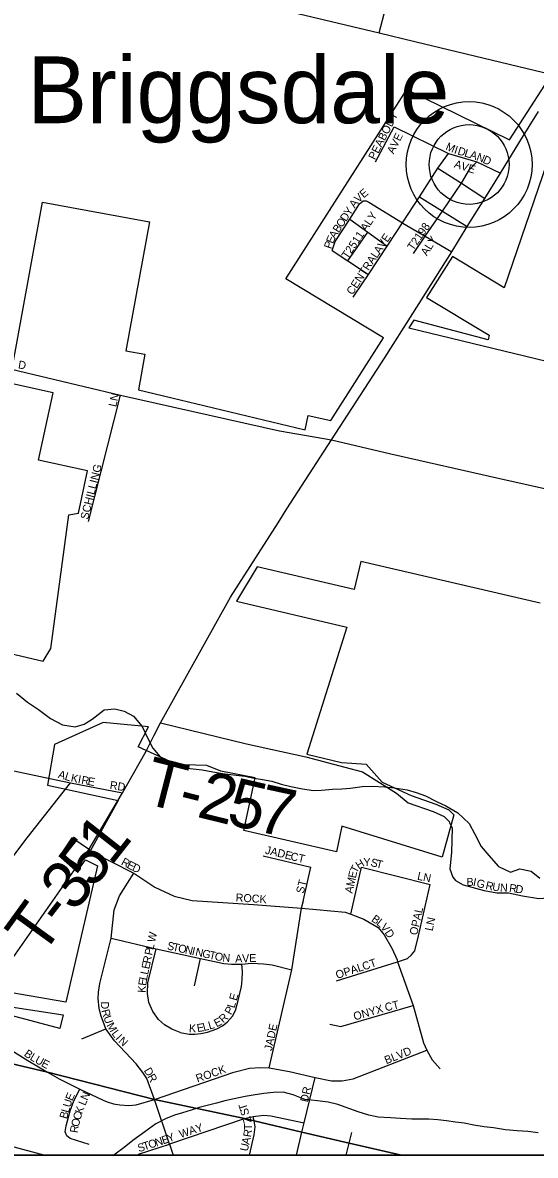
# Model space of a CAD drawing. Extents: x 0 to 34, y -6.2 to 22.
# Drawn here: x 3.061 to 3.667, y 14.39 to 15.73 of the extents above; entities that cross this region are included whole.
import ezdxf

# ---------------------------------------------------------------- set-up
doc = ezdxf.new("R2010")
doc.units = 0
for name, color, linetype in [('GM_X_City_Street', 7, 'Continuous'), ('GM_X_City_Street_Text', 7, 'Continuous'), ('GM_X_Corporation', 7, 'Continuous'), ('GM_X_County_Road', 7, 'Continuous'), ('GM_X_Minor_River', 7, 'Continuous'), ('GM_X_Township', 7, 'Continuous'), ('GM_X_Township_Road', 7, 'Continuous'), ('GM_X_Township_Road_Text', 7, 'Continuous'), ('GM_X_Township_Subdivision', 7, 'Continuous'), ('GM_X_Township_Subdivision_Text', 7, 'Continuous'), ('GM_X_Unincorporated', 7, 'Continuous'), ('GM_X_Unincorporated_Text', 7, 'Continuous'), ('GM_X_US_Route', 7, 'Continuous'), ('SH_Data', 7, 'Continuous')]:
    doc.layers.add(name, color=color, linetype=linetype)

msp = doc.modelspace()

# ---------------------------------------------------------------- linework, layer by layer
at = {"layer": 'GM_X_City_Street'}
for points in [[(2.2755, 16.0058), (2.3978, 15.9667), (2.514, 15.9401), (2.5743, 15.9266), (2.6337, 15.9133), (2.6968, 15.899), (2.7428, 15.8886), (2.791, 15.8777), (2.8428, 15.8659), (2.944, 15.8431), (3.0941, 15.8092), (3.2256, 15.7796), (3.2773, 15.7671), (3.3381, 15.7525), (3.4823, 15.7179), (3.5243, 15.7078), (3.6965, 15.6665)], [(3.4823, 15.7179), (3.5118, 15.831)], [(3.1001, 14.8344), (3.1174, 14.8308), (3.1788, 14.8191)], [(3.5655, 14.7836), (3.5685, 14.7776), (3.5675, 14.7483), (3.5658, 14.729), (3.5692, 14.7194), (3.5725, 14.7152), (3.5816, 14.7102), (3.6062, 14.7036), (3.6214, 14.7008), (3.6351, 14.7007), (3.6517, 14.6971), (3.6711, 14.6939), (3.6931, 14.6957), (3.6988, 14.6956), (3.7052, 14.6933), (3.7139, 14.691), (3.723, 14.6882), (3.724, 14.688), (3.7252, 14.6878)], [(3.1385, 14.7514), (3.1922, 14.724), (3.2168, 14.7076), (3.2398, 14.6968), (3.2609, 14.6915), (3.3334, 14.6869), (3.3904, 14.6824), (3.4081, 14.681), (3.4419, 14.6777), (3.4486, 14.6753), (3.4642, 14.6696), (3.4808, 14.6596), (3.488, 14.6512), (3.4973, 14.6352), (3.5033, 14.6214), (3.5038, 14.6193), (3.5224, 14.5673), (3.5346, 14.5232), (3.5384, 14.5145), (3.5448, 14.503), (3.5542, 14.4926)], [(3.3449, 14.7446), (3.4013, 14.7312)], [(3.3925, 14.6918), (3.3927, 14.6926), (3.4013, 14.7312)], [(3.4486, 14.6753), (3.4613, 14.7312), (3.5423, 14.7104)], [(3.2342, 14.4035), (3.2164, 14.4564), (3.2074, 14.4812), (3.2029, 14.488), (3.195, 14.4984), (3.1694, 14.5255), (3.159, 14.5398), (3.153, 14.556), (3.1512, 14.5644), (3.15, 14.5753), (3.1502, 14.5834), (3.152, 14.5933), (3.1651, 14.6471), (3.1687, 14.6806), (3.1753, 14.6972), (3.1845, 14.712), (3.1922, 14.724)], [(3.5038, 14.6193), (3.5155, 14.6232), (3.5204, 14.6274), (3.5243, 14.6323), (3.5286, 14.6497), (3.5423, 14.7104)], [(3.3521, 14.4938), (3.3788, 14.6096), (3.3904, 14.6824), (3.3925, 14.6918)], [(3.1651, 14.6471), (3.2183, 14.6344), (3.2709, 14.6229), (3.2986, 14.6171), (3.3077, 14.6162), (3.3197, 14.6164), (3.3311, 14.6174), (3.3454, 14.6169), (3.3556, 14.6154), (3.3788, 14.6096)], [(3.247, 14.5354), (3.2369, 14.5394), (3.2284, 14.5445), (3.2214, 14.5507), (3.2145, 14.5602), (3.2097, 14.5709), (3.2081, 14.5818), (3.2087, 14.5943), (3.2183, 14.6344)], [(3.2637, 14.5906), (3.2709, 14.6229)], [(3.4318, 14.5965), (3.5038, 14.6193)], [(3.247, 14.5354), (3.2575, 14.5337), (3.2642, 14.5335), (3.2714, 14.5342), (3.2791, 14.536), (3.2901, 14.5399), (3.297, 14.5433), (3.3026, 14.5478), (3.3088, 14.5547), (3.3124, 14.5616), (3.3155, 14.5732), (3.3193, 14.5901), (3.3202, 14.5977), (3.3204, 14.6078), (3.3197, 14.6164)], [(3.4237, 14.5453), (3.437, 14.5428), (3.5224, 14.5673)], [(2.9945, 14.5473), (3.0668, 14.5025), (3.0901, 14.4886), (3.1037, 14.4805), (3.1283, 14.4686), (3.156, 14.4553), (3.1605, 14.4535), (3.1682, 14.4513), (3.1756, 14.4499), (3.1861, 14.4491), (3.1949, 14.45), (3.2164, 14.4564), (3.3102, 14.4887), (3.3289, 14.4933), (3.3419, 14.4941), (3.3521, 14.4938), (3.3763, 14.4893), (3.4064, 14.4824), (3.4257, 14.4785), (3.4385, 14.4785), (3.4515, 14.4806), (3.5384, 14.5145)], [(3.1307, 14.5282), (3.159, 14.5398)], [(3.3844, 14.3902), (3.3909, 14.4178), (3.3936, 14.4288), (3.4064, 14.4824)], [(3.1393, 14.4031), (3.1169, 14.41), (3.1128, 14.4132), (3.111, 14.4181), (3.1122, 14.4249), (3.117, 14.443), (3.1212, 14.4546), (3.1283, 14.4686)], [(3.2347, 14.4037), (3.3231, 14.4338), (3.3332, 14.4362), (3.3459, 14.4378), (3.3541, 14.437), (3.3936, 14.4288)], [(3.3287, 14.3902), (3.3343, 14.4143), (3.3356, 14.4238), (3.3342, 14.4312), (3.3332, 14.4362)], [(3.4431, 14.3902), (3.4466, 14.4047), (3.4497, 14.4171)], [(3.1977, 14.3915), (3.2342, 14.4035), (3.2347, 14.4037)], [(3.2342, 14.4035), (3.2385, 14.3902)]]:
    msp.add_lwpolyline(points, dxfattribs=at)
at = {"layer": 'GM_X_Corporation'}
msp.add_line((3.0868, 14.3902), (3.8052, 14.3902), dxfattribs=at)
for points in [[(3.0189, 14.9901), (3.0848, 14.9747), (3.0939, 14.9898), (3.1154, 15.148), (3.1266, 15.1499), (3.1375, 15.1999), (3.0793, 15.2127), (3.0967, 15.2922), (3.0449, 15.3036), (3.0841, 15.5179), (3.2108, 15.4947), (3.1828, 15.3419), (3.2051, 15.3378), (3.1975, 15.2959), (3.3946, 15.2486), (3.3984, 15.2653), (3.4251, 15.2593), (3.4872, 15.3574), (3.3717, 15.4272), (3.5148, 15.651), (3.6363, 15.5914), (3.6781, 15.6561)], [(3.7056, 15.6375), (3.63, 15.4164), (3.5687, 15.4535), (3.5383, 15.4048), (3.6123, 15.3603), (3.6111, 15.3549), (3.5231, 15.3782), (3.5174, 15.369), (4.3458, 15.1683)], [(3.6725, 15.0433), (3.4604, 15.0927), (3.4527, 15.0595), (3.338, 15.0862), (3.3135, 15.0456), (3.4438, 15.0151), (3.3965, 14.8649), (3.4376, 14.8549), (3.45, 14.8541), (3.4668, 14.853), (3.4857, 14.8316), (3.5199, 14.816), (3.5493, 14.8056), (3.5644, 14.799), (3.5706, 14.7931), (3.5565, 14.743), (3.4379, 14.7797), (3.4316, 14.7494), (3.3223, 14.7746), (3.3355, 14.8369), (3.295, 14.8447), (3.2783, 14.8515), (3.2514, 14.852), (3.2351, 14.856), (3.1972, 14.8736), (3.2096, 14.897), (3.1558, 14.9022), (3.0981, 14.8761), (3.0899, 14.8279), (3.1734, 14.81), (3.1408, 14.7508), (3.1188, 14.7658), (3.106, 14.747), (3.1289, 14.7313), (3.1348, 14.7399), (3.1491, 14.7326), (3.1118, 14.5712), (3.0366, 14.5846)], [(3.0258, 14.5691), (3.1084, 14.5564), (3.1047, 14.5403), (3.0469, 14.5558)], [(2.8818, 14.3902), (2.918, 14.4415), (2.9386, 14.4646), (2.9843, 14.4515), (2.9764, 14.4198), (3.0868, 14.3902)]]:
    msp.add_lwpolyline(points, dxfattribs=at)
at = {"layer": 'GM_X_County_Road'}
for points in [[(3.0476, 15.3204), (3.1764, 15.2894), (3.3645, 15.2473), (3.4258, 15.2365)], [(3.4258, 15.2365), (3.4961, 15.2199), (3.625, 15.1908), (3.759, 15.1611), (3.7743, 15.1577), (3.7928, 15.1515), (3.84, 15.1281), (3.8645, 15.116), (3.9154, 15.0908), (3.9554, 15.0774), (4.0318, 15.0667), (4.1118, 15.0579), (4.1129, 15.0578), (4.1954, 15.041), (4.1993, 15.0402)], [(2.9923, 14.8574), (3.1001, 14.8344)]]:
    msp.add_lwpolyline(points, dxfattribs=at)
at = {"layer": 'GM_X_Minor_River'}
for points in [[(3.0532, 14.9368), (3.0664, 14.9264), (3.0795, 14.9175), (3.0934, 14.907), (3.1077, 14.8996), (3.1228, 14.8971), (3.1335, 14.9004), (3.143, 14.906), (3.1572, 14.9172)], [(3.1572, 14.9172), (3.1697, 14.9185), (3.1807, 14.9157), (3.1916, 14.9099), (3.202, 14.8976), (3.2087, 14.8834), (3.2146, 14.872), (3.225, 14.8593), (3.2355, 14.8538), (3.2453, 14.8507), (3.2586, 14.8478), (3.273, 14.8461), (3.2854, 14.844), (3.2968, 14.842), (3.313, 14.8399), (3.3233, 14.8386), (3.3342, 14.8365), (3.3444, 14.8349), (3.3554, 14.8328), (3.3663, 14.8293), (3.3777, 14.8265), (3.3916, 14.8236), (3.4045, 14.8219), (3.414, 14.8222), (3.4269, 14.8235), (3.4379, 14.8237), (3.4481, 14.8247), (3.4622, 14.8264), (3.4735, 14.8271), (3.4887, 14.8261), (3.5, 14.8248), (3.5152, 14.8227), (3.5257, 14.8195), (3.5371, 14.8156), (3.5499, 14.8089), (3.5611, 14.8035), (3.5751, 14.7953), (3.5885, 14.7826), (3.5952, 14.77), (3.6029, 14.7554), (3.6119, 14.7447), (3.6231, 14.732), (3.6374, 14.7253), (3.6484, 14.729), (3.6617, 14.7265), (3.6722, 14.718)], [(3.67, 14.417), (3.6578, 14.4183), (3.6454, 14.4192), (3.6317, 14.4205), (3.6174, 14.4226), (3.6064, 14.4239), (3.5939, 14.426), (3.5826, 14.4281), (3.5724, 14.4293), (3.5618, 14.431), (3.5515, 14.4323), (3.5409, 14.4328), (3.5209, 14.4331), (3.5072, 14.4336), (3.4955, 14.4346), (3.4811, 14.4355), (3.4698, 14.4379), (3.4573, 14.4415), (3.4332, 14.4502), (3.4218, 14.453), (3.4094, 14.4547), (3.3942, 14.4564), (3.3806, 14.4616), (3.3686, 14.4648), (3.3572, 14.4645), (3.3458, 14.4632), (3.3333, 14.4614), (3.3238, 14.4597), (3.3109, 14.4572), (3.2998, 14.4547), (3.2899, 14.4518), (3.2789, 14.4493), (3.2694, 14.4467), (3.2599, 14.4438), (3.2496, 14.4406), (3.2401, 14.4377), (3.2294, 14.4332), (3.218, 14.4273), (3.205, 14.418), (3.1908, 14.4076), (3.1805, 14.3994), (3.1701, 14.3915), (3.1683, 14.3902)]]:
    msp.add_lwpolyline(points, dxfattribs=at)
at = {"layer": 'GM_X_Township'}
msp.add_line((3.5084, 14.3902), (6.1932, 14.3902), dxfattribs=at)
for points in [[(2.2755, 14.6804), (2.2868, 14.6777), (2.9712, 14.5166), (3.0901, 14.4886), (3.2164, 14.4564), (3.3231, 14.4338), (3.3342, 14.4312), (3.3909, 14.4178), (3.4466, 14.4047), (3.5084, 14.3902)], [(2.2755, 14.6804), (2.2755, 14.3902), (3.5084, 14.3902)], [(3.5084, 14.3902), (3.4466, 14.4047), (3.3909, 14.4178), (3.3342, 14.4312), (3.3231, 14.4338), (3.2164, 14.4564), (3.0901, 14.4886), (2.9712, 14.5166), (2.2868, 14.6777), (2.2755, 14.6804)]]:
    msp.add_lwpolyline(points, dxfattribs=at)
at = {"layer": 'GM_X_Township_Road'}
for points in [[(3.2236, 14.9019), (3.3253, 14.8771), (3.3953, 14.8616), (3.4414, 14.8493), (3.4623, 14.8438), (3.5028, 14.8186), (3.5163, 14.8072), (3.5458, 14.7968), (3.5591, 14.791), (3.5643, 14.786), (3.5648, 14.7851), (3.5655, 14.7836)], [(2.9201, 14.6707), (2.9389, 14.6668), (2.9731, 14.6616), (2.9923, 14.6583), (2.9939, 14.6649), (3.0029, 14.6849), (3.0115, 14.6955), (3.0258, 14.713), (3.0658, 14.7658), (3.1174, 14.8308)]]:
    msp.add_lwpolyline(points, dxfattribs=at)
at = {"layer": 'GM_X_Township_Subdivision'}
for points in [[(3.4777, 15.5654), (3.4997, 15.6067)], [(3.4997, 15.6067), (3.5643, 15.5754), (3.5977, 15.5653), (3.6255, 15.5522)], [(3.5022, 15.4818), (3.5097, 15.4933), (3.5297, 15.5241), (3.5516, 15.5579), (3.5643, 15.5754)], [(3.5228, 15.4572), (3.5366, 15.4774), (3.5569, 15.5072), (3.5793, 15.5401), (3.5891, 15.5565), (3.5977, 15.5653)], [(3.5516, 15.5579), (3.5793, 15.5401), (3.6071, 15.5222)], [(3.4264, 15.4605), (3.4276, 15.464), (3.4303, 15.4712), (3.4473, 15.4978), (3.4587, 15.5158), (3.4633, 15.5192)], [(3.4633, 15.5192), (3.4667, 15.5192), (3.4701, 15.5176), (3.5097, 15.4933), (3.5102, 15.493), (3.5366, 15.4774), (3.5679, 15.4591)], [(3.5297, 15.5241), (3.5569, 15.5072), (3.5863, 15.489)], [(3.4473, 15.4978), (3.4687, 15.4822), (3.4915, 15.4657)], [(3.4452, 15.4482), (3.4687, 15.4822)], [(3.4627, 15.4223), (3.4694, 15.4323), (3.4915, 15.4657), (3.5022, 15.4818), (3.5022, 15.4818)], [(3.4264, 15.4605), (3.4452, 15.4482), (3.4694, 15.4323)], [(3.4514, 15.4052), (3.4627, 15.4223), (3.4627, 15.4223)], [(3.1385, 15.14), (3.1764, 15.2894)]]:
    msp.add_lwpolyline(points, dxfattribs=at)
at = {"layer": 'GM_X_Unincorporated'}
for radius in [0.0744, 0.0472]:
    msp.add_circle((3.5885, 15.5623), radius, dxfattribs=at)
at = {"layer": 'GM_X_US_Route'}
for points in [[(3.6243, 15.5503), (3.6255, 15.5522), (3.6486, 15.5896), (3.6707, 15.625)], [(3.4843, 15.3267), (3.4885, 15.3332), (3.5221, 15.3861), (3.5679, 15.4591), (3.5863, 15.489), (3.6071, 15.5222), (3.6243, 15.5503)], [(3.3626, 15.1386), (3.3729, 15.1548), (3.4258, 15.2365), (3.4843, 15.3267)], [(3.2161, 14.8871), (3.2236, 14.9019), (3.3064, 15.0506), (3.3626, 15.1386)], [(3.2074, 14.8698), (3.2161, 14.8871)], [(3.1836, 14.8275), (3.2067, 14.8684), (3.2074, 14.8698)], [(3.1408, 14.7553), (3.1788, 14.8191), (3.1836, 14.8275)], [(3.135, 14.7465), (3.1385, 14.7514), (3.1408, 14.7553)], [(2.9881, 14.5388), (2.9945, 14.5473), (3.0467, 14.6204), (3.135, 14.7465)]]:
    msp.add_lwpolyline(points, dxfattribs=at)
at = {"layer": 'SH_Data'}
msp.add_lwpolyline([(9.0755, 21.1902), (9.0755, 14.3902), (2.2755, 14.3902), (2.2755, 21.1902)], close=True, dxfattribs=at)

# ---------------------------------------------------------------- texts
at = {"layer": 'GM_X_City_Street_Text'}
for s, rotation, p in [('D', 350.2289, (3.0548, 15.3213)), ('A', 343.0789, (3.1018, 14.837)), ('L', 343.0872, (3.1097, 14.8346)), ('K', 347.8693, (3.117, 14.8325)), ('I', 349.559, (3.1254, 14.8306)), ('R', 349.6937, (3.1295, 14.8299)), ('E', 349.6932, (3.1369, 14.8285)), ('RD', 351.0327, (3.1632, 14.8238)), ('JADE', 346.3728, (3.3467, 14.7472)), ('R', 331.469, (3.1763, 14.7345)), ('CT', 347.4648, (3.3766, 14.7397)), ('H', 31.9943, (3.4579, 14.7283)), ('Y', 1.58, (3.4637, 14.7323)), ('S', 346.3728, (3.4714, 14.7326)), ('T', 346.3728, (3.4778, 14.731)), ('E', 331.455, (3.1829, 14.7309)), ('D', 334.1463, (3.1892, 14.7275)), ('E', 77.6158, (3.4545, 14.7174)), ('T', 62.4086, (3.4557, 14.7233)), ('ST', 75.9573, (3.3928, 14.6992)), ('M', 77.6158, (3.4523, 14.7076)), ('LN', 348.1073, (3.5266, 14.7164)), ('B', 1.7489, (3.5856, 14.7088)), ('I', 348.2442, (3.5925, 14.7091)), ('G', 345.2375, (3.5965, 14.7082)), ('R', 347.2109, (3.6073, 14.7054)), ('U', 351.8179, (3.6154, 14.7036)), ('ROCK', 356.4997, (3.3123, 14.6906)), ('A', 77.6158, (3.4505, 14.6995)), ('N', 358.3377, (3.6249, 14.7023)), ('R', 352.4744, (3.6354, 14.702)), ('D', 351.2023, (3.6428, 14.7011)), ('B', 324.9423, (3.4722, 14.6678)), ('OPAL', 77.4718, (3.527, 14.65)), ('L', 321.2335, (3.4782, 14.6636)), ('V', 309.9707, (3.483, 14.6598)), ('LN', 78.1183, (3.5453, 14.655)), ('W', 77.8031, (3.2171, 14.6416)), ('D', 304.2114, (3.4882, 14.6536)), ('P', 77.806, (3.2137, 14.6262)), ('L', 77.7793, (3.2152, 14.6327)), ('S', 347.6668, (3.2308, 14.6339)), ('T', 347.6668, (3.2373, 14.6324)), ('O', 347.6442, (3.2438, 14.631)), ('N', 347.6618, (3.252, 14.6292)), ('I', 347.6182, (3.2601, 14.6275)), ('N', 347.684, (3.2642, 14.6266)), ('G', 347.6442, (3.2723, 14.6248)), ('E', 77.8138, (3.2102, 14.6099)), ('R', 77.7899, (3.2116, 14.6164)), ('T', 347.6644, (3.2805, 14.623)), ('O', 347.6656, (3.287, 14.6216)), ('N', 355.9282, (3.2966, 14.6196)), ('A', 2.3395, (3.312, 14.6181)), ('V', 2.3493, (3.3203, 14.6184)), ('E', 1.1201, (3.3286, 14.6188)), ('CT', 19.4394, (3.464, 14.6088)), ('L', 77.7793, (3.2088, 14.6033)), ('OPAL', 17.9243, (3.4324, 14.5988)), ('E', 82.9055, (3.2067, 14.5904)), ('L', 78.6418, (3.2075, 14.5968)), ('K', 85.9751, (3.2061, 14.5822)), ('E', 73.7313, (3.3136, 14.5725)), ('D', 272.6671, (3.153, 14.572)), ('P', 60.5137, (3.3069, 14.5557)), ('L', 73.715, (3.311, 14.5637)), ('ONYX', 16.1457, (3.4532, 14.5497)), ('CT', 13.2348, (3.49, 14.5605)), ('R', 284.1466, (3.1537, 14.5617)), ('U', 290.2566, (3.1559, 14.5534)), ('E', 27.9631, (3.2899, 14.5415)), ('R', 42.6607, (3.2979, 14.5462)), ('M', 299.6919, (3.1595, 14.544)), ('L', 307.936, (3.1652, 14.5341)), ('K', 359.1912, (3.2572, 14.5358)), ('E', 9.4647, (3.2674, 14.5359)), ('L', 14.0851, (3.2748, 14.5371)), ('L', 16.4924, (3.2816, 14.5389)), ('JADE', 78.0242, (3.3553, 14.5133)), ('I', 312.6288, (3.1699, 14.5282)), ('N', 316.7562, (3.1732, 14.5246)), ('B', 324.612, (3.0615, 14.5085)), ('BLVD', 21.8014, (3.4906, 14.4979)), ('L', 329.8033, (3.0684, 14.5037)), ('U', 331.4894, (3.0744, 14.5002)), ('E', 331.562, (3.0818, 14.4962)), ('D', 300.5365, (3.2036, 14.4906)), ('R', 297.7597, (3.2078, 14.4835)), ('ROCK', 19.1814, (3.2673, 14.4763)), ('E', 66.1235, (3.1193, 14.4539)), ('N', 65.8111, (3.1371, 14.4544)), ('DR', 77.4789, (3.3978, 14.4525)), ('L', 73.4019, (3.115, 14.4398)), ('U', 72.5951, (3.1169, 14.4462)), ('K', 70.5212, (3.1309, 14.4383)), ('L', 67.2246, (3.1346, 14.4483)), ('T', 107.0975, (3.327, 14.4452)), ('S', 107.0582, (3.3289, 14.4388)), ('B', 73.3775, (3.1129, 14.4326)), ('O', 75.3276, (3.1268, 14.4232)), ('C', 74.108, (3.1289, 14.4312)), ('Z', 104.9126, (3.3315, 14.4296)), ('R', 80.362, (3.1256, 14.4161)), ('WAY', 17.8768, (3.2474, 14.4105)), ('R', 80.6623, (3.3305, 14.4112)), ('T', 89.9956, (3.3318, 14.4202)), ('S', 18.0548, (3.1982, 14.3938)), ('T', 18.0548, (3.2045, 14.3959)), ('O', 18.071, (3.2109, 14.398)), ('N', 18.071, (3.2188, 14.4005)), ('E', 18.5611, (3.2268, 14.4031)), ('Y', 21.0294, (3.2335, 14.4054)), ('A', 77.1805, (3.3285, 14.4024)), ('U', 77.1512, (3.3266, 14.3943))]:
    msp.add_text(s, height=0.00947, rotation=rotation, dxfattribs=at).set_placement(p)
at = {"layer": 'GM_X_Township_Road_Text'}
for s, rotation, p in [('T', 345.5376, (3.2008, 14.8075)), ('2', 346.1931, (3.2652, 14.7909)), ('5', 346.915, (3.3, 14.7824)), ('-', 345.7027, (3.2421, 14.7968)), ('7', 347.7562, (3.3349, 14.7743)), ('1', 51.8124, (3.1652, 14.7316)), ('5', 51.8384, (3.1436, 14.7041)), ('3', 51.9164, (3.122, 14.6766)), ('T', 54.0593, (3.0831, 14.6242)), ('-', 52.1887, (3.1078, 14.6582))]:
    msp.add_text(s, height=0.0568, rotation=rotation, dxfattribs=at).set_placement(p)
at = {"layer": 'GM_X_Township_Subdivision_Text'}
for s, rotation, p in [('PEABODY', 63.048, (3.4772, 15.5671)), ('AVE', 63.4349, (3.4992, 15.574)), ('M', 335.9931, (3.5599, 15.5802)), ('I', 342.3225, (3.5701, 15.5757)), ('D', 343.2255, (3.5742, 15.5744)), ('L', 343.2066, (3.5822, 15.572)), ('A', 342.8989, (3.5885, 15.5701)), ('N', 338.2595, (3.5963, 15.5677)), ('D', 335.86, (3.6039, 15.5647)), ('A', 342.1663, (3.5701, 15.5591)), ('V', 342.2914, (3.5781, 15.5566)), ('E', 342.8733, (3.5861, 15.554)), ('E', 40.1064, (3.4638, 15.5221)), ('A', 54.2844, (3.4533, 15.5101)), ('V', 42.697, (3.4578, 15.5165)), ('D', 57.2254, (3.443, 15.4941)), ('T2511 ALY', 55.8414, (3.4448, 15.4498)), ('Y', 57.2254, (3.4475, 15.5011)), ('B', 57.2327, (3.4344, 15.4808)), ('O', 57.2254, (3.4384, 15.4871)), ('T2198', 55.0104, (3.5223, 15.4598)), ('E', 65.8545, (3.4275, 15.4679)), ('A', 58.3166, (3.43, 15.4737)), ('E', 56.3781, (3.4919, 15.4696)), ('ALY', 57.387, (3.5385, 15.4535)), ('P', 71.1071, (3.4254, 15.4618)), ('A', 58.3352, (3.4831, 15.4556)), ('V', 57.4433, (3.4874, 15.4626)), ('CENTRAL', 56.5609, (3.4506, 15.4073)), ('LN', 77.4763, (3.1712, 15.275)), ('SCHILLING', 75.7727, (3.1379, 15.1417))]:
    msp.add_text(s, height=0.00947, rotation=rotation, dxfattribs=at).set_placement(p)
at = {"layer": 'GM_X_Unincorporated_Text'}
msp.add_text('Briggsdale', height=0.07898, rotation=0, dxfattribs=at).set_placement((3.0662, 15.6112))

doc.saveas('drawing.dxf')
